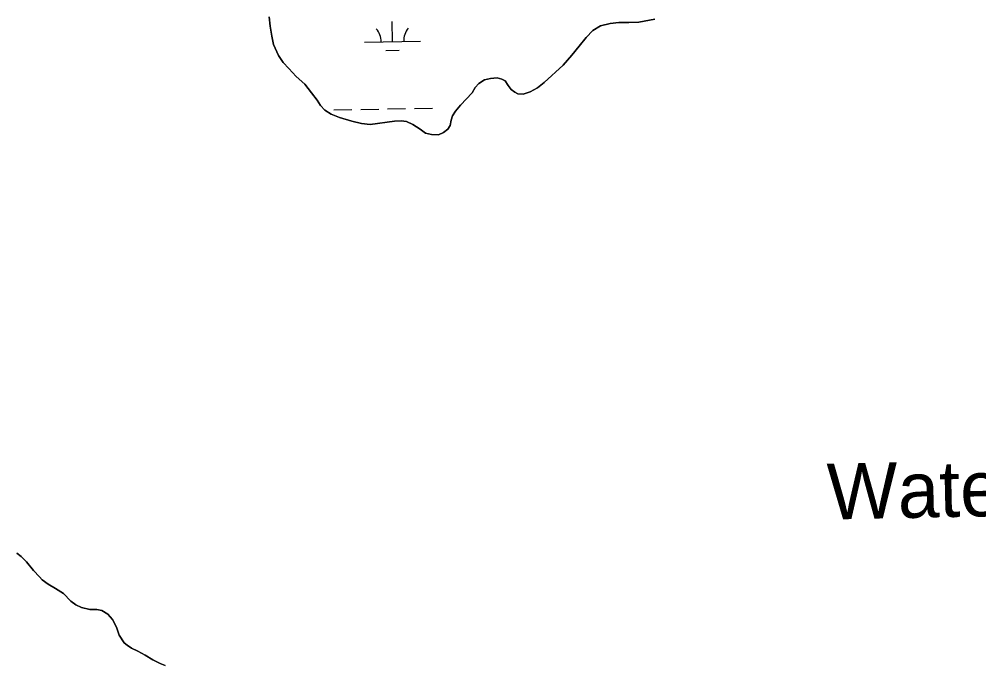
# Model space of a CAD drawing. Extents: x 3914892 to 3953151, y 242587 to 268572.
# Drawn here: x 3946155 to 3947870, y 256282 to 257434 of the extents above; entities that cross this region are included whole.
import ezdxf

# ---------------------------------------------------------------- set-up
doc = ezdxf.new("R2010")
doc.units = 0
for name, color, linetype in [('V-RIVR-IDEN', 7, 'Continuous'), ('V-TOPO-SHOR', 7, 'Continuous'), ('V-WETL-SWMP', 7, 'Continuous')]:
    doc.layers.add(name, color=color, linetype=linetype)

msp = doc.modelspace()

# ---------------------------------------------------------------- linework, layer by layer
at = {"layer": 'V-TOPO-SHOR'}
for points in [[(3946601.6, 257438.6), (3946603.4, 257421.9), (3946606.5, 257404.1), (3946609.6, 257389.1), (3946618.7, 257369.1), (3946627.1, 257357), (3946637.1, 257346.1), (3946650, 257331.9), (3946665.4, 257318), (3946677.5, 257302.5), (3946687.4, 257289.6), (3946693.5, 257280.1), (3946701.1, 257271.4), (3946712.8, 257264.5), (3946727.6, 257258.7), (3946749.4, 257251.8), (3946766.9, 257248.1), (3946782.6, 257246.3), (3946825.7, 257252), (3946837.7, 257252.7), (3946847, 257251.3), (3946858.5, 257246.2), (3946871.5, 257237.6), (3946881.2, 257230.3), (3946891.7, 257227.9), (3946904.3, 257227.6), (3946913.5, 257231.6), (3946921.1, 257237.7), (3946925, 257244.4), (3946926.8, 257253.5), (3946929.7, 257261.4), (3946934.8, 257269.7), (3946943.5, 257280.6), (3946964.3, 257302.8), (3946969.9, 257312.2), (3946976.3, 257319.3), (3946986.8, 257325.9), (3946997.2, 257328.2), (3947009.2, 257329.6), (3947017.7, 257327.3), (3947023.2, 257324), (3947029.1, 257315.5), (3947034.2, 257308.7), (3947040.5, 257303.6), (3947046.2, 257300.9), (3947055.7, 257300.2), (3947068.2, 257304.2), (3947081, 257311.6), (3947092.9, 257320.8), (3947127.2, 257352.1), (3947142.6, 257370.2), (3947155.8, 257385.8), (3947168.2, 257401.5), (3947180, 257414.3), (3947194, 257422.5), (3947211, 257426.6), (3947226.4, 257428.1), (3947244.3, 257428.3), (3947262.6, 257429), (3947291, 257434.2)], [(3946415.9, 256279), (3946406.9, 256282.7), (3946394.3, 256289.1), (3946380.1, 256297.4), (3946367, 256304.6), (3946356, 256310.3), (3946347.9, 256315.4), (3946343, 256319.7), (3946334, 256333.4), (3946329, 256347.4), (3946322.1, 256361.6), (3946313.6, 256371.1), (3946302.8, 256377.3), (3946293.8, 256379.2), (3946281.3, 256379.2), (3946266.4, 256383), (3946256.3, 256387.5), (3946247.8, 256394.4), (3946234.3, 256407.6), (3946219.9, 256416.6), (3946206.9, 256424.7), (3946196.6, 256432), (3946191.3, 256437.5), (3946180.9, 256449.2), (3946168.6, 256464.3), (3946159, 256473.8), (3946150.9, 256479.9)]]:
    msp.add_lwpolyline(points, dxfattribs=at)
at = {"layer": 'V-WETL-SWMP'}
for p, q in [((3946603.4, 257421.9), (3946601.6, 257438.6)), ((3946606.5, 257404.1), (3946603.4, 257421.9)), ((3946822.1, 257394.1), (3946821.5, 257430.1)), ((3947194, 257422.5), (3947180, 257414.3)), ((3947211, 257426.6), (3947194, 257422.5)), ((3947226.4, 257428.1), (3947211, 257426.6)), ((3947244.3, 257428.3), (3947226.4, 257428.1)), ((3947262.6, 257429), (3947244.3, 257428.3)), ((3947291, 257434.2), (3947262.6, 257429)), ((3946609.6, 257389.1), (3946606.5, 257404.1)), ((3947180, 257414.3), (3947168.2, 257401.5)), ((3946618.7, 257369.1), (3946609.6, 257389.1)), ((3946772.2, 257393.2), (3946872.1, 257395)), ((3947168.2, 257401.5), (3947155.8, 257385.8)), ((3946627.1, 257357), (3946618.7, 257369.1)), ((3946810.4, 257378.5), (3946834.4, 257378.9)), ((3947142.6, 257370.2), (3947127.2, 257352.1)), ((3947155.8, 257385.8), (3947142.6, 257370.2)), ((3946637.1, 257346.1), (3946627.1, 257357)), ((3947127.2, 257352.1), (3947092.9, 257320.8)), ((3946650, 257331.9), (3946637.1, 257346.1)), ((3946665.4, 257318), (3946650, 257331.9)), ((3946677.5, 257302.5), (3946665.4, 257318)), ((3946976.3, 257319.3), (3946969.9, 257312.2)), ((3946986.8, 257325.9), (3946976.3, 257319.3)), ((3946997.2, 257328.2), (3946986.8, 257325.9)), ((3947009.2, 257329.6), (3946997.2, 257328.2)), ((3947017.7, 257327.3), (3947009.2, 257329.6)), ((3947023.2, 257324), (3947017.7, 257327.3)), ((3947029.1, 257315.5), (3947023.2, 257324)), ((3947092.9, 257320.8), (3947081, 257311.6)), ((3946687.4, 257289.6), (3946677.5, 257302.5)), ((3946964.3, 257302.8), (3946943.5, 257280.6)), ((3946969.9, 257312.2), (3946964.3, 257302.8)), ((3947034.2, 257308.7), (3947029.1, 257315.5)), ((3947040.5, 257303.6), (3947034.2, 257308.7)), ((3947046.2, 257300.9), (3947040.5, 257303.6)), ((3947055.7, 257300.2), (3947046.2, 257300.9)), ((3947068.2, 257304.2), (3947055.7, 257300.2)), ((3947081, 257311.6), (3947068.2, 257304.2)), ((3946693.5, 257280.1), (3946687.4, 257289.6)), ((3946701.1, 257271.4), (3946693.5, 257280.1)), ((3946712.8, 257264.5), (3946701.1, 257271.4)), ((3946717.5, 257272.1), (3946749.5, 257272.7)), ((3946765.5, 257273), (3946797.5, 257273.6)), ((3946813.4, 257273.9), (3946845.4, 257274.4)), ((3946861.4, 257274.7), (3946893.4, 257275.3)), ((3946934.8, 257269.7), (3946929.7, 257261.4)), ((3946943.5, 257280.6), (3946934.8, 257269.7)), ((3946727.6, 257258.7), (3946712.8, 257264.5)), ((3946749.4, 257251.8), (3946727.6, 257258.7)), ((3946766.9, 257248.1), (3946749.4, 257251.8)), ((3946825.7, 257252), (3946782.6, 257246.3)), ((3946837.7, 257252.7), (3946825.7, 257252)), ((3946847, 257251.3), (3946837.7, 257252.7)), ((3946858.5, 257246.2), (3946847, 257251.3)), ((3946926.8, 257253.5), (3946925, 257244.4)), ((3946929.7, 257261.4), (3946926.8, 257253.5)), ((3946782.6, 257246.3), (3946766.9, 257248.1)), ((3946871.5, 257237.6), (3946858.5, 257246.2)), ((3946881.2, 257230.3), (3946871.5, 257237.6)), ((3946921.1, 257237.7), (3946913.5, 257231.6)), ((3946925, 257244.4), (3946921.1, 257237.7)), ((3946891.7, 257227.9), (3946881.2, 257230.3)), ((3946904.3, 257227.6), (3946891.7, 257227.9)), ((3946913.5, 257231.6), (3946904.3, 257227.6)), ((3946150.9, 256479.9), (3946159, 256473.8)), ((3946159, 256473.8), (3946168.6, 256464.3)), ((3946168.6, 256464.3), (3946180.9, 256449.2)), ((3946180.9, 256449.2), (3946191.3, 256437.5)), ((3946191.3, 256437.5), (3946196.6, 256432)), ((3946196.6, 256432), (3946206.9, 256424.7)), ((3946206.9, 256424.7), (3946219.9, 256416.6)), ((3946219.9, 256416.6), (3946234.3, 256407.6)), ((3946234.3, 256407.6), (3946247.8, 256394.4)), ((3946247.8, 256394.4), (3946256.3, 256387.5)), ((3946256.3, 256387.5), (3946266.4, 256383)), ((3946266.4, 256383), (3946281.3, 256379.2)), ((3946281.3, 256379.2), (3946293.8, 256379.2)), ((3946293.8, 256379.2), (3946302.8, 256377.3)), ((3946302.8, 256377.3), (3946313.6, 256371.1)), ((3946313.6, 256371.1), (3946322.1, 256361.6)), ((3946322.1, 256361.6), (3946329, 256347.4)), ((3946329, 256347.4), (3946334, 256333.4)), ((3946334, 256333.4), (3946343, 256319.7)), ((3946343, 256319.7), (3946347.9, 256315.4)), ((3946347.9, 256315.4), (3946356, 256310.3)), ((3946356, 256310.3), (3946367, 256304.6)), ((3946367, 256304.6), (3946380.1, 256297.4)), ((3946380.1, 256297.4), (3946394.3, 256289.1)), ((3946394.3, 256289.1), (3946406.9, 256282.7)), ((3946406.9, 256282.7), (3946415.9, 256279))]:
    msp.add_line(p, q, dxfattribs=at)
for centre, start, end in [((3946766.9, 257393.6), 0.2532, 41.7968), ((3946877.4, 257395.6), 140.2532, 181.7968)]:
    msp.add_arc(centre, 35.2, start, end, dxfattribs=at)

# ---------------------------------------------------------------- texts
at = {"layer": 'V-RIVR-IDEN'}
msp.add_text('Water', height=100, rotation=1.2267, dxfattribs=at).set_placement((3947599.5, 256539.9))

doc.saveas('drawing.dxf')
